Omron CX-Programmer project NewProject (CX-Programmer 9.43)

# PLC NewPLC1: CJ2M CPU12
I/O table (CPU CJ2M-CPU12): rack 0 slot 0 CJ1W-SCU42

## Program NewProgram1 (cyclic task 0)
Local symbols
CodeData 5505 WORD
CommPortEnabledFlag_P7 A202.07 BOOL
Input_Start 5000.00 BOOL
Local_ControlWord1 5010 UINT
Local_ControlWord2 5011 UINT
Local_FirstReceiveWord 5500 UINT
Local_FirstSendWord 5020 UINT
Local_PMCRError 5000.07 BOOL
Local_PMCRErrorEnd 5000.05 BOOL
Local_PMCRExecuting 5000.01 BOOL
Local_PMCRNormalEnd 5000.04 BOOL
Local_PMCR_ErrorCode 5012 UINT
Local_ResponseCode 5501 UINT
NumberOfDigits 5504 WORD
Output_ErrorEnd 5000.03 BOOL
Output_NormalEnd 5000.02 BOOL
Output_PMCR_ErrorCode H400 UINT
ProtocolMacroErrorCode_SCU_0_P2 1519 UINT
ProtocolMacroExecuting_SCU_0_P2 1519.15 BOOL
ReceiveData_First 5501 WORD
ReceiveData_Last 5750 WORD
ReceiveError 5501 WORD
SequenceAbortEndCompletion_SCU_0_P2 1519.10 BOOL
SequenceEndCompletion_SCU_0_P2 1519.11 BOOL
TransmissionErrorStatus_SCU_0_P2 1518 WORD
TransmissionError_SCU_0_P2 1518.15 BOOL
reserve_ReadCount 5503 WORD
reserve_ReceiveCount 5502 WORD

### Section Section1

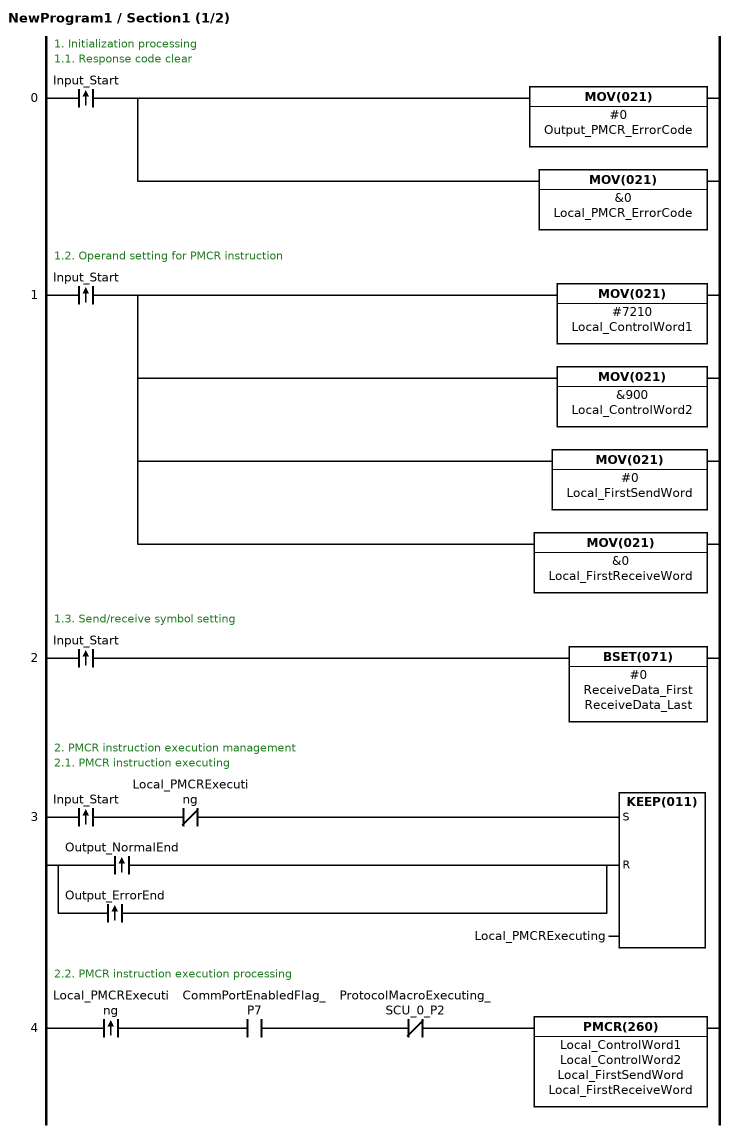
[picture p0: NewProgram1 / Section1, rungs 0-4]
; rung 0: 1. Initialization processing / 1.1. Response code clear
@LD Input_Start
MOV(021) #0 Output_PMCR_ErrorCode
MOV(021) &0 Local_PMCR_ErrorCode
; rung 1: 1.2. Operand setting for PMCR instruction
@LD Input_Start
MOV(021) #7210 Local_ControlWord1
MOV(021) &900 Local_ControlWord2
MOV(021) #0 Local_FirstSendWord
MOV(021) &0 Local_FirstReceiveWord
; rung 2: 1.3. Send/receive symbol setting
@LD Input_Start
BSET(071) #0 ReceiveData_First ReceiveData_Last
; rung 3: 2. PMCR instruction execution management / 2.1. PMCR instruction executing
@LD Input_Start
ANDNOT Local_PMCRExecuting
@LD Output_NormalEnd
@OR Output_ErrorEnd
KEEP(011) Local_PMCRExecuting
; rung 4: 2.2. PMCR instruction execution processing
@LD Local_PMCRExecuting
AND CommPortEnabledFlag_P7
ANDNOT ProtocolMacroExecuting_SCU_0_P2
PMCR(260) Local_ControlWord1 Local_ControlWord2 Local_FirstSendWord Local_FirstReceiveWord

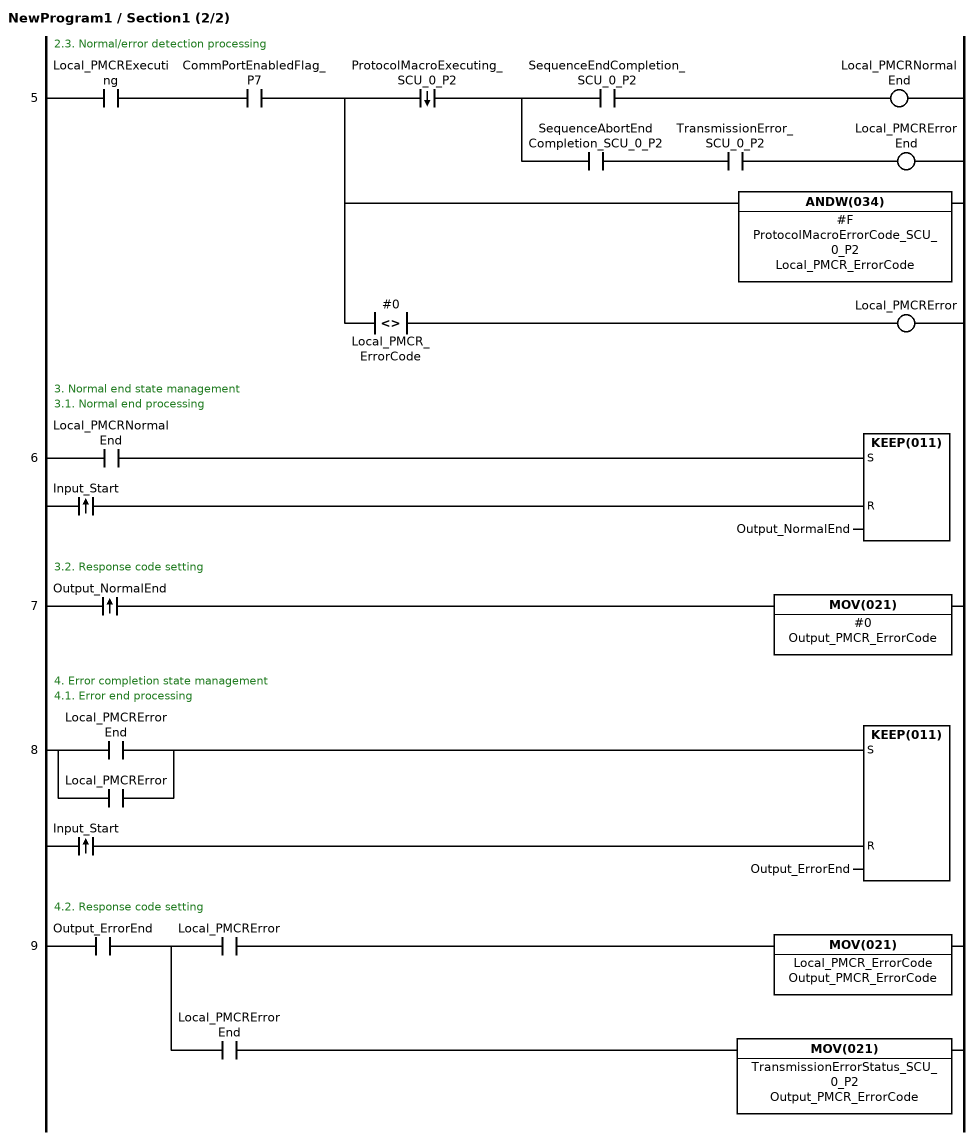
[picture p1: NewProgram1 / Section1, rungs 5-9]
; rung 5: 2.3. Normal/error detection processing
LD Local_PMCRExecuting
AND CommPortEnabledFlag_P7
OUT TR0
%AND ProtocolMacroExecuting_SCU_0_P2
OUT TR1
AND SequenceEndCompletion_SCU_0_P2
OUT Local_PMCRNormalEnd
LD TR1
AND SequenceAbortEndCompletion_SCU_0_P2
AND TransmissionError_SCU_0_P2
OUT Local_PMCRErrorEnd
LD TR0
ANDW(034) #F ProtocolMacroErrorCode_SCU_0_P2 Local_PMCR_ErrorCode
AND<>(305) #0 Local_PMCR_ErrorCode
OUT Local_PMCRError
; rung 6: 3. Normal end state management / 3.1. Normal end processing
LD Local_PMCRNormalEnd
@LD Input_Start
KEEP(011) Output_NormalEnd
; rung 7: 3.2. Response code setting
@LD Output_NormalEnd
MOV(021) #0 Output_PMCR_ErrorCode
; rung 8: 4. Error completion state management / 4.1. Error end processing
LD Local_PMCRErrorEnd
OR Local_PMCRError
@LD Input_Start
KEEP(011) Output_ErrorEnd
; rung 9: 4.2. Response code setting
LD Output_ErrorEnd
OUT TR0
AND Local_PMCRError
MOV(021) Local_PMCR_ErrorCode Output_PMCR_ErrorCode
LD TR0
AND Local_PMCRErrorEnd
MOV(021) TransmissionErrorStatus_SCU_0_P2 Output_PMCR_ErrorCode

### Section END
; rung 0
END(001)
